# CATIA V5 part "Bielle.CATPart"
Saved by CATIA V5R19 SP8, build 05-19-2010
Part number: Bielle
Publications: "Longueur bielle"
Bounding box of the stored display mesh (mm): x -87.5 to 335, y -139.961 to 2225, z -139.961 to 375
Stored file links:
  C:\Users\rcousturie\Desktop\EU_thinkMotion\iao\IAO_MMS_Groupe1\flacan\flacan\flacan\Bielle.CATPart
  C:\Users\rcousturie\Desktop\EU_thinkMotion\iao\IAO_MMS_Groupe1\flacan\flacan\flacan\Jambe.CATPart
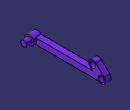
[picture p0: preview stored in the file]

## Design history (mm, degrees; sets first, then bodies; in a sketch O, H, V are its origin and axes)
Parameters
  `Longueur bielle` = 2100 mm
Body1 (main body)
  Sketch1 on xy-plane, origin (0, 0, 0), H (1, 0, 0), V (0, 1, 0)
    line L1 (160, 87.5) -> (335, 87.5)
    line L2 (335, 87.5) -> (335, 0)
    line L3 (160, 140) -> (-87.5, 140)
    line L4 (160, 140) -> (160, 87.5)
    line L5 (335, 0) -> (-87.5, 0)
    line L6 (-87.5, 0) -> (-87.5, 140)
    length L1 = 175
    distance L4 V = 160
    length L2 = 87.5
    length L6 = 140
    distance L6 V = 87.5
    distance L3 H = 140
    horizontal: L1 H, L3 H, L5 H
    vertical: L2 V, L4 V, L6 V
  Line1: type PtDir, RefPoint Sketch1.O, Direction yz-plane, Start 0, End 20
  Shaft1: profile Sketch1, axis Line1, angle 360
  Point1: (0, 2100 {= `Longueur bielle`}, 0)
  Sketch2 on yz-plane, origin (0, 0, 0), H (0, 1, 0), V (0, 0, 1)
    point P1 (2100, 0)
    reference projected point E1 (2100, 0) from Point1
    line L1 (2010.7233, -87.5) -> (0, -87.5)
    line L2 (0, -87.5) -> (0, 87.5)
    line L3 (0, 87.5) -> (1835.7233, 87.5)
    point P4 (1850, 250)
    construction line L4 (2100, -126.2294) -> (2100, 147.9931)
    axis line L5 (1985.9595, 0) -> (2285.5903, 0)
    point P7 (1985.9595, 0)
    reference projected point E2 (2100, 0) from Point1
    arc A1 centre (2100, 0) radius 125 from (2011.6117, -88.3883) to (2188.3883, 88.3883) ccw
    point P11 (2100, 0)
    reference projected point E3 (2100, 0) from Point1
    arc A2 centre (1850, 250) radius 125 from (1938.3883, 338.3883) to (1761.6117, 161.6117) ccw
    line L6 (2188.3883, 88.3883) -> (1938.3883, 338.3883)
    line L7 (2011.6117, -88.3883) -> (2010.7233, -87.5)
    line L8 (1835.7233, 87.5) -> (1761.6117, 161.6117)
    distance P1 E1 = 0
    distance L1 P1 = 87.5
    distance L1 L3 = 175
    distance L5 P4 = 250
    distance L4 P4 = 250
    distance L4 E2 = 0
    radius A1 = 125
    distance P11 E3 = 0
    radius A2 = 125
    distance L2 L4 = 2100 {= `Longueur bielle`}
    horizontal: L1 H, L3 H, L5 H
    vertical: L2 V, L4 V
    coincidence: P7 H, L7 L8
    tangency: L6 A1, L6 A2, L7 A1, L7 A2
  Pad1: profile Sketch2, direction (1, 0, 0), length 87.5, opposite side length 87.5
  Sketch3 on end face of Pad1, origin (87.5, 0, 0), H (0, 1, 0), V (0, 0, 1)
    circle A1 centre (2100, 0) radius 87.5
    point P1 (2100, 0)
    circle A2 centre (1850, 250) radius 87.5
    point P2 (1850, 250)
    reference projected point E1 (2100, 0) from Point1
    construction line L1 (2100, -87.5) -> (2100, 87.5)
    point P3 (2100, -87.5)
    point P4 (2100, 87.5)
    axis line L2 (2187.5, 0) -> (2012.5, 0)
    point P5 (2187.5, 0)
    point P6 (2012.5, 0)
    radius A1 = 87.5
    radius A2 = 87.5
    distance P1 E1 = 0
    distance L1 P2 = 250
    distance P2 L2 = 250
    length L1 = 175
    coincidence: P3 A1, P4 A1, P5 H, P5 A1, P6 A1
    vertical: L1 V
    horizontal: L2 H
  Pocket1: profile Sketch3, direction (-1, 0, 0), through (limit type 6)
